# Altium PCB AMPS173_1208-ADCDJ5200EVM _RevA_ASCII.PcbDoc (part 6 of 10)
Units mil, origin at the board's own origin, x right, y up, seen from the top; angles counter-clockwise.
Board outline 10500 x 2750 mil, 14 copper layers (Top Copper, Layer 2 (GND1), Layer 3 (SIG1), Layer 4 (GND2, Layer 5 (PWR1), Layer 6 (GND3), Layer 7 (PWR/SIGNAL2), Layer 8 (PWR/SIGNAL3), Layer 9 (GND4), Layer 10 PWR2), Layer 11 (GND5), Layer 12 (SIG4), Layer 13 (GND6), Bottom Copper), stack 60.6 mil thick; 701 components, 826 nets, 3386 pads, 2128 vias.
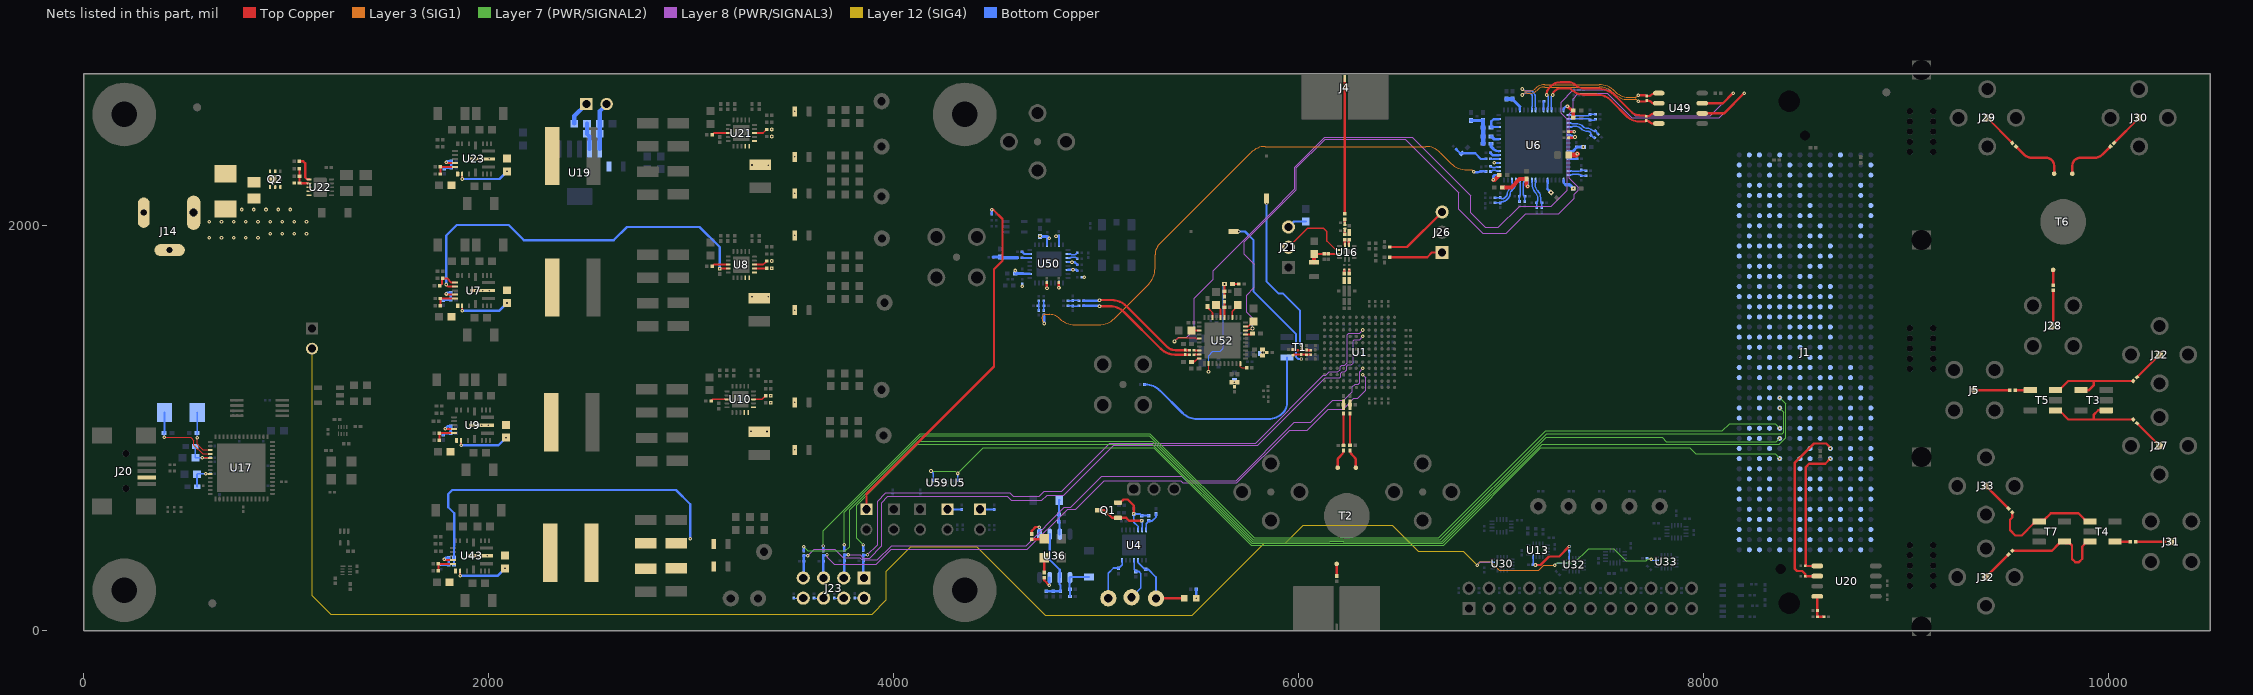
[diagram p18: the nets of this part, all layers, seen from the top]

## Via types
v1: diameter 18, hole 8, Top Copper to Bottom Copper, tented both sides, 1234 vias
v2: diameter 18, hole 8, Top Copper to Bottom Copper, tented top, 219 vias
v3: diameter 16, hole 8, Top Copper to Bottom Copper, tented both sides, 138 vias
v4: diameter 19.68, hole 7.87, Top Copper to Bottom Copper, 103 vias
v5: diameter 20, hole 10, Top Copper to Bottom Copper, tented top, 96 vias
v6: diameter 20, hole 10, Top Copper to Bottom Copper, tented both sides, 71 vias
v7: diameter 15.75/18/18/18/16/18/18/18/18/16/18/18/18/18 (per signal layer), hole 8, Top Copper to Bottom Copper, 50 vias
v8: diameter 20, hole 10, Top Copper to Bottom Copper, 40 vias
v9: diameter 15.75, hole 7.87, Top Copper to Bottom Copper, 28 vias
v10: diameter 21.81, hole 10, Top Copper to Bottom Copper, 26 vias
v11: diameter 15.75/16/16/16/16/16/16/16/16/16/16/16/16/18 (per signal layer), hole 8, Top Copper to Bottom Copper, 26 vias
v12: diameter 18, hole 8, Top Copper to Bottom Copper, tented bottom, 18 vias
v13: diameter 25.75, hole 15.75, Top Copper to Bottom Copper, 16 vias
v14: diameter 15.75/16/16/16/16/16/16/18/16/16/16/16/16/18 (per signal layer), hole 8, Top Copper to Bottom Copper, 15 vias
v15: diameter 30, hole 15, Top Copper to Bottom Copper, tented both sides, 12 vias
v16: diameter 15.75/16/16/16/18/16/16/16/16/16/16/16/16/18 (per signal layer), hole 8, Top Copper to Bottom Copper, 11 vias
v17: diameter 15.75/16/16/16/16/16/16/16/16/18/16/16/16/18 (per signal layer), hole 8, Top Copper to Bottom Copper, 7 vias
v18: diameter 15.75/16/16/16/16/16/16/18/16/18/16/16/16/18 (per signal layer), hole 8, Top Copper to Bottom Copper, 5 vias
v19: diameter 119.29, hole 77.95, Top Copper to Bottom Copper, 4 vias
v20: diameter 18, hole 8, Top Copper to Bottom Copper, 4 vias
v21: diameter 15.75/16/16/16/18/16/16/18/16/16/16/16/16/18 (per signal layer), hole 8, Top Copper to Bottom Copper, 2 vias
v22: diameter 15.75/16/16/16/16/16/18/16/16/16/16/16/16/18 (per signal layer), hole 8, Top Copper to Bottom Copper, 2 vias
v23: diameter 15.75/16/16/16/16/16/18/18/16/16/16/16/16/18 (per signal layer), hole 8, Top Copper to Bottom Copper, 1 vias

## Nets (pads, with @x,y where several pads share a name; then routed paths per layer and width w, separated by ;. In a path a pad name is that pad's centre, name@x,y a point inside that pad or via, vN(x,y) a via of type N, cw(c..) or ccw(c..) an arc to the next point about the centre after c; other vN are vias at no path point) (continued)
LMK_REF_P: C49.2 C507.1 R451.2 | length 2767
  Layer 3 (SIG1) w3.25: v1(4743.41,1517.62) 4740.27,1520.76 cw(c4760.17,1540.65) 4732.03,1540.65 4732.03,1547.03 cw(c4747,1547.03) 4747,1562 4769.46,1562 cw(c4769.46,1490.46) 4820.05,1541.05 ccw(c4893.18,1614.18) 4893.18,1510.75 5011.58,1510.75 ccw(c5011.58,1622) 5090.24,1543.33 5257.95,1711.05 ccw(c5179.99,1789.01) 5290.25,1789.01 5290.25,1857.26 cw(c5364.51,1857.26) 5312,1909.77 5763.94,2361.71 cw(c5834.65,2291) 5834.65,2391 6627.58,2391 cw(c6627.58,2291) 6698.29,2361.71 6751.67,2308.33 ccw(c6830.33,2387) 6830.33,2275.75 6853,2275.75 cw(c6853,2270.56) 6856.66,2274.24 v1(6864.58,2266.32)
  Bottom Copper w10.5: C507.1@4740,1558.98 cw(c4732.76,1551.73) 4743,1551.73 4743,1518.61 ccw(c4744.4,1518.61) v1(4743.41,1517.62) ; v1(6864.58,2266.32) ccw(c6868.97,2270.7) 6868.97,2264.5 6883.97,2264.5 ccw(c6883.97,2279.78) 6894.78,2268.98 R451.2@6900,2268.98 6911.69,2268.98 ccw(c6914.04,2271.33) 6914.04,2268 C49.2@6925,2268
LMX_CPOUT: C337.1 C338.1 R263.2 U52.12 | length 590.7
  Top Copper w6: U52.12@5554.13,1319.2 5554.21,1319.13 v1(5554.21,1278.79)
  Top Copper w10: R263.2@5633.21,1650.79 C338.1@5633.21,1676.79 v1(5633.21,1712.48) C337.1@5633.52,1712.79
  Bottom Copper w5: v1(5554.21,1278.79) 5554.21,1359.21 5575,1380 5612,1380 5626,1394 5626,1705.27 v1(5633.21,1712.48)
LMX_REF_N: C347.2 C506.1 R265.1 | length 615.5
  Top Copper w11.5: v1(5016,1603) 5066.58,1603 cw(c5066.58,1503) 5137.29,1573.71 5317.94,1393.06 ccw(c5388.65,1463.77) 5388.65,1363.77 R265.1@5439.21,1363.77 C347.2@5460.21,1363.79
  Bottom Copper w11.5: C506.1@4936.02,1605 5014,1605 v1(5016,1603)
LMX_REF_P: C346.2 C505.1 R265.2 | length 620.8
  Top Copper w11.5: v1(5016,1633) 5077.58,1633 cw(c5077.58,1533) 5148.29,1603.71 5348,1404 ccw(c5391.89,1447.89) 5391.89,1385.82 R265.2@5439.21,1385.82 C346.2@5460.21,1385.79
  Bottom Copper w11.5: C505.1@4936.02,1630 5013,1630 v1(5016,1633)
LMX_SYNC: U49.7 U52.5 | length 4574.9
  Top Copper w5: v1(5386.21,1428.79) 5404.21,1446.79 5489.21,1446.79 5492.78,1443.22 U52.5@5508.86,1443.22
  Top Copper w11.5: U49.7@7992.28,2605 8095,2605 v1(8145,2655)
  Layer 8 (PWR/SIGNAL3) w3.3: v1(5386.21,1428.79) 5406.41,1449 5447,1449 5485,1487 5485,1643 5577,1735 5577,1778.28 5921,2122.28 5921,2124.47 5980.35,2183.82 5980.35,2289.23 6129.12,2438 6560.54,2438 6849.85,2148.69 6849.85,2063.69 6921.54,1992 6985,1992 7090,2097 7246,2097 7325,2176 7325,2526 7295,2556 7295,2611 7356,2672 7533,2672 7662,2543 8033,2543 v1(8145,2655)
LMX_SYSREFREQ: U49.6 U52.28 | length 4460.5
  Top Copper w4: U52.28@5737.21,1482.59 5746,1482.59 5752.21,1488.79 5767.21,1488.79 v1(5771.21,1492.79)
  Top Copper w11.5: U49.6@7992.28,2555 8100,2555 v1(8200,2655)
  Layer 8 (PWR/SIGNAL3) w3.3: v1(5771.21,1492.79) 5771.21,1544.79 5742,1574 5742,1657 5781,1696 5781,1810 5731,1860 5731,1920.55 5988.65,2178.19 5988.65,2285.79 6130.85,2428 6525.54,2428 6790.85,2162.69 6790.85,2081 6907.85,1964 7024,1964 7120.16,2060.16 7283.16,2060.16 7359.45,2136.45 7359.45,2155.78 7379.35,2175.68 7379.35,2190 7335,2234.35 7335,2552.15 7355,2572.15 7355,2628 7381,2654 7524,2654 7645.5,2532.5 8077.5,2532.5 v1(8200,2655)
LMX_VTUNE: C336.1 R263.1 U52.35 | length 77.4
  Top Copper w8: U52.35@5632.87,1547.55 5632.87,1597.46 C336.1@5633.21,1597.79
  Top Copper w10: C336.1@5633.21,1597.79 R263.1@5633.21,1624.8
NCOA0_ADC: J23.1 R83.1 R84.2 U1.C7 | length 3269.9
  Layer 8 (PWR/SIGNAL3) w3.3: v3(3870,375) 3920,425 3920,640 3961,681 4573.01,681 4590,664 4719,664 4744,689 4829,689 5066.7,926.7 5786.7,926.7 6121,1261 6133,1261 6151.41,1279.41 6193.64,1279.41 6204.41,1290.19 6204.41,1303.41 6213,1312 6226.22,1312 6238.11,1323.88 6238.11,1461.11 6246.39,1469.39 6299.9,1469.39 v14(6315.75,1485.24)
  Bottom Copper w11.5: J23.1@3853,261 3850,264 R84.2@3850,345 3848.98,346.02 R83.1@3848.98,373.98 3868.98,373.98 v3(3870,375)
NCOA0_FMC: J1.H25 R83.2 | length 5579.3
  Layer 7 (PWR/SIGNAL2) w3.3: v3@3849.48,423.47 v3@3849.98,423.98
  Layer 7 (PWR/SIGNAL2) w4: v3(3848.98,423.98) 3817,455.95 3817,620.95 4118,921.95 5277.06,921.95 5767.84,431.18 6157.21,431.18 6158.17,432.14 6215.83,432.14 6216.79,431.18 6710.4,431.18 7201.18,921.95 8372,921.95 8404,953.95 8404,1121 v1(8375,1150)
  Bottom Copper w11.5: R83.2@3848.98,396.02 v3(3848.98,423.98)
NCOA1_ADC: J23.3 R87.1 R89.2 U1.D7 | length 3364.4
  Layer 8 (PWR/SIGNAL3) w3.3: v3(3775,375) 3834,375 3849.75,359.25 3880.26,359.25 3940,418.99 3940,632.99 3971.01,664 4561.01,664 4581,644 4731,644 4757,670 4840,670 5086.7,916.7 5796.7,916.7 6130.11,1250.11 6203.11,1250.11 6206.61,1253.61 6206.61,1272.02 6214,1279.41 6226.41,1279.41 6237,1290 6237,1307 6243,1313 6260,1313 6268,1321 6268,1431 6275,1438 6301.02,1438 v14@6316.76,1453.74
  Bottom Copper w11.5: J23.3@3753,261 3756.02,264.02 R89.2@3756.02,346.02 3755,347.05 R87.1@3755,375 v3(3775,375)
  other v14: 6315.75,1453.74
NCOA1_FMC: J1.H26 R87.2 | length 5546.8
  Layer 7 (PWR/SIGNAL2) w3.3: v3(3755,425) 3755,426.01 v3@3756.01,425
  Layer 7 (PWR/SIGNAL2) w4: v3@3755,426.01 3755,584.41 4133.54,962.95 5261.52,962.95 5775.29,449.18 6149.75,449.18 6150.72,450.14 6223.28,450.14 6224.25,449.18 6698.65,449.18 7223.43,973.95 8388,973.95 8395,980.95 8395,1080 v1(8375,1100)
  Bottom Copper w11.5: R87.2@3755,397.05 v3(3755,425)
NCOB0_ADC: J23.5 R91.1 R108.2 U1.K7 | length 3266.2
  Layer 8 (PWR/SIGNAL3) w3.3: v3@3671.01,375 3671.01,363 3705.5,328.5 3913.51,328.5 3987.01,402 4659.5,402 4858,600.5 4899.5,600.5 5040.25,741.25 5416.75,741.25 5427,731 5694.54,731 5954.23,990.69 6042.77,990.69 6146.48,1094.4 6219.07,1094.4 6272.22,1147.55 6291.94,1147.55 6331.4,1187 6331.4,1250.12 v14@6316.76,1264.76
  Bottom Copper w11.5: J23.5@3653,261 3652.4,261.6 R108.2@3652.4,343.19 3652.4,371.14 R91.1@3651.38,372.17 3667.17,372.17 v3(3670,375)
  other v14: 6315.75,1264.76
NCOB0_FMC: J1.H28 R91.2 | length 5480.1
  Layer 7 (PWR/SIGNAL2) w4: v3(3651.38,418.62) 3651.38,493.52 4129.81,971.95 5265.24,971.95 5779.02,458.18 6146.02,458.18 6146.99,459.14 6227.01,459.14 6227.98,458.18 6691.75,458.18 7220.73,987.16 8092.21,987.16 8128,1022.95 8352.05,1022.95 v1(8375,1000)
  Bottom Copper w11.5: v3@3650,420 v3(3651.38,418.62) R91.2@3651.38,394.21
NCOB1_ADC: J23.7 R109.1 R147.2 U1.J7 | length 3364
  Layer 8 (PWR/SIGNAL3) w3.3: v3@3576.01,370 3608.01,402 3709.01,402 3751.11,359.9 3833.1,359.9 3843.25,349.75 3918.76,349.75 3990.01,421 4653,421 4842,610 4874,610 5027.5,763.5 5422.5,763.5 5444,742 5690.16,742 5977.85,1029.69 6059.2,1029.69 6166.91,1137.4 6222.49,1137.4 6265,1179.91 6265,1204.65 6277.97,1217.62 6292.72,1217.62 6300.1,1225 6300.1,1279.6 v14@6316.76,1296.26
  Bottom Copper w11.5: J23.7@3553,261 3556.02,264.02 R147.2@3556.02,342.98 ; R147.2@3555,344 R109.1@3555,371.95 3573.05,371.95 v3(3575,370)
  other v14: 6315.75,1296.26
NCOB1_FMC: J1.H29 R109.2 | length 5619
  Layer 7 (PWR/SIGNAL2) w3.3: v3@3556.01,415 v3@3555.5,414.5 ; v3@3555.5,414.5 3555,413.99 v3(3555,415) v3@3555.5,414.5
  Layer 7 (PWR/SIGNAL2) w4: v3@3555.5,414.5 3576.05,393.95 3761,393.95 3782,414.95 3782,598.68 4119.27,935.95 5275.79,935.95 5771.56,440.18 6153.48,440.18 6154.44,441.14 6219.56,441.14 6220.52,440.18 6706.67,440.18 7221.45,954.95 7794,954.95 7814.95,934 8359,934 v1(8375,950)
  Bottom Copper w11.5: R109.2@3555,394 v3(3555,415)
NetC1_1: C1.1 U6.37 | length 42.3
  Bottom Copper w8: C1.1@6946.02,2330 6946.69,2329.33 6957.87,2329.33 6958.54,2330 6987.09,2330 U6.37@6987.09,2329.33
NetC1_2: C1.2 R30.2 R32.2 | length 165.7
  Bottom Copper w11.5: R32.2@6777.79,2377.2 6797.11,2357.89 R30.2@6804.7,2357.89 6804.93,2357.67 6871.33,2357.67 6899,2330 C1.2@6923.98,2330
NetC4_1: C4.1 R20.2 U4.7 | length 109.2
  Bottom Copper w9: U4.7@5246.31,498.28 5246.31,529.54 C4.1@5259.25,542.48 5276.75,542.48 5295,560.73 R20.2@5295,577.01
NetC4_2: C4.2 C5.2 Q1.2 R21.2 U4.5 | length 303.2
  Top Copper w11.5: Q1.2@5107.24,632.4 5118.4,632.4 5134,648 5155,648 5185,618 v1(5185,577.01)
  Bottom Copper w9: U4.5@5206.94,498.28 5206.94,515 5185,536.94 v1(5185,577.01) 5215.71,577.01 C5.2@5224.25,568.46 C4.2@5259.25,568.46
NetC5_1: C5.1 Q1.1 Q1.3 U4.6 | length 278.4
  Top Copper w11.5: Q1.3@5012.76,595 5040,595 5077.4,557.6 Q1.1@5107.24,557.6 5147.4,557.6 5162.52,542.48 v1(5224.25,542.48)
  Bottom Copper w9: v1(5224.25,542.48) 5226.62,540.11 U4.6@5226.62,498.28
NetC6_1: C6.1 U6.38 | length 45.6
  Bottom Copper w11.5: C6.1@6946.02,2360 6957.01,2349.02 U6.38@6987.09,2349.02
NetC7_1: C7.1 C228.1 FB3.1 FB5.1 FB6.1 FB7.1 R135.2 U21.1 U21.19 U21.20
  other v1: 3510.57,1953.02 3510.57,2160.02 3379.15,2299.13 3300,2300 3510.57,2340.02 3397.99,2440.75 3397.99,2475.75 3510.57,2565.02
NetC45_1: C45.1 C73.2 R1.2 R171.1 R172.2 | length 88.1
  Top Copper w11.5: C45.1@5972.02,1359.98 cw(c5981.62,1350.38) 5981.62,1363.95 R172.2@6013,1363.95 R171.1@6059,1364 R171.1@6059,1364
NetC46_1: C46.1 C98.2 R2.2 R172.1 R174.1 | length 87.8
  Top Copper w12: C46.1@5972.02,1389 ccw(c5979.27,1396.24) 5979.27,1386 C98.2@6013,1386 R174.1@6059,1386
NetC47_1: C47.1 C48.1 L3.2 U6.10 U6.33 U6.36 | length 188.3
  Top Copper w20: v1(6960.46,2226.81) 6967.13,2226.81 C47.1@6990.31,2250
  Bottom Copper w10: v1(6966,2312) ccw(c6970.24,2316.24) 6970.24,2310.24 U6.36@6987.09,2310.24
  Bottom Copper w11.5: 6960.46,2245.46 6965.59,2250.59 U6.33@6987.09,2250.59 ; U6.10@7333.54,2368.7 7353.7,2368.7
  Bottom Copper w15: v1(6960.46,2226.81) 6960.46,2245.46 ; 7353.7,2368.7 7373.98,2388.98 v1(7405,2388.98)
NetC49_1: C49.1 U6.34 | length 42.3
  Bottom Copper w7: C49.1@6947.05,2268 cw(c6960.84,2254.2) 6960.84,2273.71 6968.93,2273.71 cw(c6968.93,2264.01) 6975.8,2270.87 U6.34@6987.09,2270.87
NetC50_1: C50.1 U6.35 | length 42.2
  Bottom Copper w7: C50.1@6947.05,2293 ccw(c6959.81,2305.76) 6959.81,2287.71 6968.93,2287.71 ccw(c6968.93,2297.42) 6975.8,2290.56 U6.35@6987.09,2290.56
NetC53_2: C53.2 L4.2 U6.17 | length 72
  Top Copper w11.5: v1(7355,2185.32) C53.2@7355.31,2185
  Bottom Copper w11.5: U6.17@7307.95,2225 7307.95,2212.05 7317.5,2202.5
  Bottom Copper w15: 7317.5,2202.5 7337.81,2202.5 v1(7355,2185.32) L4.2@7355.31,2185
NetC54_2: C54.2 L5.2 U6.21 | length 68.9
  Bottom Copper w11.5: 7228.15,2209.7 7229.21,2210.76 U6.21@7229.21,2225 ; v1(7245.77,2164.23) C54.2@7246.08,2163.92
  Bottom Copper w12: 7228.15,2181.85 7228.15,2209.7
  Bottom Copper w15: 7228.15,2181.85 v1(7245.77,2164.23)
NetC55_2: C55.2 L7.2 U6.26 | length 204.7
  Top Copper w20: L7.2@7004.69,2190 7050,2190 7090.31,2230.31 C55.2@7125,2230.31 7125,2200 v1(7130,2195)
  Bottom Copper w11.5: v1(7130,2195) 7130.79,2195.79 U6.26@7130.79,2225
NetC56_2: C56.2 L11.2 U6.53 | length 98.9
  Bottom Copper w11.5: U6.53@7091.42,2571.46 7091.42,2588.9
  Bottom Copper w15: L11.2@7055,2625.31 7091.42,2588.9
  Bottom Copper w20: C56.2@7025,2625.31 L11.2@7055,2625.31
NetC57_2: C57.2 L12.2 U6.64 | length 101
  Top Copper w15.5: v1(7326.65,2590.63) 7347.28,2570 L12.2@7355.31,2570 C57.2@7355.31,2535
  Bottom Copper w10: U6.64@7307.95,2571.46 7307.95,2572.25 cw(c7325.75,2572.25) v1@7325.75,2590.05
NetC58_1: C58.1 C59.1 L6.2 L8.1 L9.1 L10.1 | length 176.6
  Bottom Copper w11.5: L6.2@6850,2520.31 L6.2@6851.34,2518.98 ; C58.1@6908.66,2518.98 C58.1@6910,2520.32 ; L10.1@6910,2485.31 L10.1@6910.31,2485
  Bottom Copper w15: L6.2@6851.34,2518.98 C59.1@6880,2518.98 C58.1@6908.66,2518.98
  Bottom Copper w20: L10.1@6910,2485.31 C58.1@6910,2520.32
  Bottom Copper w22: L8.1@6910.31,2405 L10.1@6910.31,2485
NetC64_1: C64.1 U6.11 | length 88.4
  Top Copper w25: C64.1@7332.56,2350 7370,2350 v1(7375,2355)
  Bottom Copper w11.5: U6.11@7333.54,2349.02 7369.02,2349.02 v1(7375,2355)
NetC65_1: C65.1 U6.12 | length 40.7
  Bottom Copper w11.5: U6.12@7333.54,2329.33 7373.31,2329.33 C65.1@7373.98,2330
NetC67_1: C67.1 U43.2 | length 260.7
  Top Copper w9.8: v1(1858.9,271.1) U43.2@1858.9,295.2
  Bottom Copper w11.5: v1(1858.9,271.1) 2042.6,271.1 v1(2080,308.5)
NetC67_2: C67.2 L27.1 U43.9
  other v9: 1926.61,370 1959.29,370 1991.97,370
NetC73_1: C73.1 J11.1 | length 785.5
  Bottom Copper w10: v3(5703.35,1971.69) 5734.26,1971.69 5776,1929.95 5776,1676.25 5986,1466.25 5986,1352.95 5997.05,1341.91 v3(6013,1341.91)
NetC74_1: C74.1 C90.1 R22.1 | length 158
  Top Copper w11.5: C74.1@6221,915.02 R22.1@6221,1073.01
NetC75_1: C75.1 T2.1 | length 60
  Top Copper w11.5: C75.1@6187,270.04 T2.1@6187,330.04
NetC83_1: C83.1 C84.2 L14.2 U17.9 | length 149.5
  Top Copper w6: v1(602.47,774.97) U17.9@624.82,774.97
  Bottom Copper w8: C83.1@560,772.5 562.47,774.97 v1(602.47,774.97) C84.2@624.93,774.97
  Bottom Copper w10: L14.2@559.62,711.5 560,711.87 C83.1@560,772.5
NetC85_1: C85.1 C86.2 L15.2 U17.5 | length 171.7
  Top Copper w8: v1(584.71,853.71) U17.5@624.82,853.71
  Bottom Copper w8: C85.1@550.5,853.5 C85.1@550.71,853.71 ; L15.2@551.12,910.5 551.12,854.13 C85.1@550.71,853.71 ; C86.2@624.98,853.5 584.93,853.5 v1(584.71,853.71) C85.1@550.71,853.71
NetC87_1: C87.1 U17.3 Y1.1 | length 235.1
  Top Copper w5: v1(560,953) 560,921 587.92,893.08 U17.3@624.82,893.08
  Bottom Copper w5: C87.1@559.68,977 560,976.68 v1(560,953)
  Bottom Copper w8: Y1.1@558.98,1076.98 Y1.1@560,1078 560,977.32 C87.1@559.68,977
NetC88_1: C88.1 U17.4 Y1.2 | length 400.1
  Top Copper w5: v1(397,955) 528,955 544,939 544,917 587.6,873.4 U17.4@624.82,873.4
  Bottom Copper w5: C88.1@396.32,976 397,975.32 v1(397,955)
  Bottom Copper w8: C88.1@396.32,976 398.58,978.27 Y1.2@398.58,1078 Y1.2@397.61,1077.02
NetC90_2: C90.2 T2.3 | length 95
  Top Copper w11.5: T2.3@6192,805.04 6192,841.51 cw(c6212.49,841.51) 6198,856 6213.19,871.19 ccw(c6194.35,890.04) C90.2@6221,890.04
NetC91_1: C91.1 C93.1 R23.1 | length 157
  Top Copper w11.5: C91.1@6253,916.02 R23.1@6253,1073.01
NetC91_2: C91.2 T2.2 | length 95
  Top Copper w11.5: C91.2@6253,890.04 ccw(c6279.65,890.04) 6260.81,871.19 6276,856 cw(c6261.51,841.51) 6282,841.51 T2.2@6282,805.04
NetC92_1: C92.1 R215.2 R217.2 U20.8 | length 133.2
  Top Copper w11.5: U20.8@8560.31,170 8561.02,169.29 C92.1@8561.02,100 R217.2@8561.02,70 R215.2@8593.98,70
NetC94_1: C94.1 C95.1 C97.1 FB1.2 U16.9 | length 165.8
  Top Copper w10: C97.1@6076,1860.49 6076.51,1861 C94.1@6126,1861 C95.1@6146,1861 6146.75,1860.25 U16.9@6200.66,1860.25
  Top Copper w20: FB1.2@6076,1819.87 C97.1@6076,1860.49
NetC98_1: C98.1 J9.1 | length 785.5
  Bottom Copper w10: v3(5841.12,2109.45) 5841.12,1723.84 5899,1665.95 5921,1665.95 6005,1581.95 6005,1416.05 v3(6013,1408.05)
NetC99_1: C99.1 R181.1
NetC99_2: C99.2 R180.2 | length 18
  Top Copper w11.5: C99.2@6248.92,1763.99 R180.2@6248.92,1782.01
NetC101_1: C101.1 C102.1 C103.1 C104.1 C117.1 FB2.1 FB8.1 L27.2 R229.2 | length 1764.9
  Bottom Copper w11.5: C117.1@1827.99,325 R229.2@1827.99,360 1827.99,417.99 1829.25,419.25 1829.25,580.75 1800,610 1800,675 1820,695 2925,695 2995,625 v1(2995,455)
NetC105_1: C105.1 R186.1
NetC105_2: C105.2 R185.2 | length 18
  Top Copper w11.5: C105.2@6224.92,1763.99 R185.2@6224.92,1782.01
NetC106_2: C106.2 L13.1 R6.2 | length 16.9
  Top Copper w11.5: C106.2@6227.23,2015.72 R6.2@6227.23,2032.62
NetC107_1: C107.1 U16.6 | length 22.8
  Top Copper w11.5: U16.6@6227.23,1906.51 C107.1@6227.23,1929.35
NetC107_2: C107.2 C118.2 L13.2 | length 17
  Top Copper w11.5: C107.2@6227.23,1957.49 C118.2@6227.23,1974.49
NetC108_1: C108.1 U16.5 | length 28.9
  Top Copper w10: C108.1@6246.92,1929.35 C108.1@6249.08,1931.51 ; C108.1@6246.92,1931.51 C108.1@6249.08,1929.35
  Top Copper w11.5: U16.5@6246.92,1906.51 C108.1@6246.92,1929.35
NetC108_2: C108.2 R193.2 | length 16.5
  Top Copper w10: R193.2@6246.84,1973.94 6246.84,1957.57 C108.2@6246.92,1957.49
NetC115_2: C115.2 R228.1 U43.22 | length 107.5
  Top Copper w9.8: C115.2@1750.98,295.75 R228.1@1750.98,330.75 1751.1,330.63 U43.22@1823.46,330.63
NetC116_2: C116.2 U43.1
NetC117_2: C117.2 R229.1 R232.2 U43.21 | length 149.3
  Top Copper w9.8: v1(1780,353.37) 1776.74,353.37 1779.8,350.31 U43.21@1823.46,350.31
  Bottom Copper w11.5: R232.2@1765,327.99 1767.99,325 C117.2@1802.01,325 R229.1@1802.01,360 1786.63,360 v1(1780,353.37)
NetC119_1: C119.1 T5.6 | length 75
  Top Copper w11.5: C119.1@9537.5,1188.48 T5.6@9612.5,1188.48
NetC119_2: C119.2 J5.1 | length 175
  Top Copper w11.5: J5.1@9336.52,1188.48 C119.2@9511.52,1188.48
NetC120_1: C120.1 J22.1 | length 157.9
  Top Copper w11.5: C120.1@10139.25,1251.86 J22.1@10250.87,1363.48
NetC120_2: C120.2 T3.6 T5.1 | length 496.8
  Top Copper w11.5: T5.1@9737.5,1188.48 9755,1188.48 9800,1233.48 9939.52,1233.48 10116.2,1233.48 10116.76,1232.93 10120.32,1232.93 C120.2@10120.87,1233.48 ; T3.6@9862.5,1188.48 9902.48,1188.48 9925,1211 9925,1233.48
NetC121_1: C121.1 J27.1 | length 157.9
  Top Copper w11.5: C121.1@10139.25,1025.11 J27.1@10250.87,913.48
NetC121_2: C121.2 T3.3 T5.3 | length 496.8
  Top Copper w11.5: T5.3@9737.5,1088.48 9755,1088.48 9800,1043.48 9925,1043.48 ; T3.3@9987.5,1088.48 9947.52,1088.48 9925,1065.97 9925,1043.48 ; C121.2@10120.87,1043.48 10120.32,1044.04 10116.76,1044.04 10116.2,1043.48 9925,1043.48
NetC122_1: C122.1 T6.1 | length 75
  Top Copper w11.5: C122.1@9725,1706.98 T6.1@9725,1781.98
NetC122_2: C122.2 J28.1 | length 175
  Top Copper w11.5: J28.1@9725,1506 C122.2@9725,1681
NetC123_1: C123.1 T6.3 | length 270.6
  Top Copper w11.5: C123.1@9542.12,2390.85 9581.4,2351.56 ccw(c9619,2389.19) 9619,2336 9690.98,2336 cw(c9690.98,2296.98) 9730,2296.98 T6.3@9730,2256.98
NetC123_2: C123.2 J29.1 | length 175
  Top Copper w11.5: J29.1@9400,2532.97 C123.2@9523.74,2409.22
NetC127_1: C127.1 T6.2 | length 270.6
  Top Copper w11.5: T6.2@9820,2256.98 9820,2296.98 cw(c9859.02,2296.98) 9859.02,2336 9931,2336 ccw(c9931,2389.19) 9968.6,2351.56 C127.1@10007.88,2390.85
NetC127_2: C127.2 J30.1 | length 175
  Top Copper w11.5: C127.2@10026.26,2409.22 J30.1@10150,2532.97
NetC129_1: C129.1 U7.2 | length 260.7
  Top Copper w9.8: v1(1868.9,1581.1) U7.2@1868.9,1605.2
  Bottom Copper w11.5: v1(1868.9,1581.1) 2052.6,1581.1 v1(2090,1618.5)
NetC129_2: C129.2 L1.1 U7.9
  other v9: 1936.61,1680 1969.29,1680 2001.97,1680
NetC136_2: C136.2 R93.1 U7.22 | length 107.5
  Top Copper w9.8: C136.2@1760.98,1605.75 R93.1@1760.98,1640.75 1761.1,1640.63 U7.22@1833.46,1640.63
NetC137_2: C137.2 U7.1
NetC138_1: C138.1 T4.6 | length 75
  Top Copper w11.5: T4.6@10031.5,440 C138.1@10106.5,440
NetC138_2: C138.2 J31.1 | length 175
  Top Copper w11.5: C138.2@10132.48,440 J31.1@10307.48,440
NetC143_2: C143.2 R96.1 R97.2 U7.21 | length 152.5
  Top Copper w9.8: v1(1790,1663.37) 1786.74,1663.37 1789.8,1660.32 U7.21@1833.46,1660.31
  Bottom Copper w11.5: R97.2@1775,1632.99 1777.01,1635 C143.2@1812.01,1635 R96.1@1812.01,1670 1796.63,1670 v1(1790,1663.37) v1@1790,1667
NetC144_1: C144.1 U8.13 | length 82.4
  Top Copper w9: C144.1@3102.99,1800 3110.99,1808 U8.13@3182.04,1808
NetC148_1: C148.1 J32.1 | length 157.9
  Top Copper w11.5: J32.1@9393.13,265 C148.1@9504.75,376.63
NetC148_2: C148.2 T4.1 T7.6 | length 562.2
  Top Copper w11.5: C148.2@9523.13,395 9523.68,395.56 9719.56,395.56 9754.75,430.75 9764,440 T7.6@9781.5,440 9790.75,430.75 9808.25,430.75 9818,421 9818,355 9834,339 9852.6,339 9869,355.4 9869,415.99 9879.75,426.74 9879.75,430.75 9889,440 T4.1@9906.5,440
NetC149_1: C149.1 J33.1 | length 157.9
  Top Copper w11.5: J33.1@9393.13,715 C149.1@9504.75,603.37
NetC149_2: C149.2 T4.3 T7.3 | length 560.9
  Top Copper w11.5: C149.2@9523.13,585 9523.68,584.44 9523.68,580.88 9523.13,580.33 9523.13,559.31 9511.95,548.14 9511.95,497.08 9538.26,470.78 9569.78,470.78 9629.75,530.75 9639,540 T7.3@9656.5,540 9665.75,549.25 9683.25,549.25 9714,580 9850,580 9879.75,550.25 9879.75,549.25 9889,540 T4.3@9906.5,540
NetC164_1: C164.1 C244.1 FB9.1 R98.2 U8.1 U8.19 U8.20
  other v1: 3510.57,1583.02 3379.15,1649.13 3300,1650 3397.99,1790.75 3397.99,1825.75
NetC164_2: C164.2 U8.3 | length 67.4
  Top Copper w9: U8.3@3311.96,1808 3354.26,1808 C164.2@3372.01,1825.75
NetC165_1: C165.1 U9.2 | length 260.7
  Top Copper w9.8: v1(1863.9,916.1) U9.2@1863.9,940.2
  Bottom Copper w11.5: v1(1863.9,916.1) 2047.6,916.1 v1(2085,953.5)
NetC165_2: C165.2 L2.1 U9.9
  other v9: 1931.61,1015 1964.29,1015 1996.97,1015
NetC192_2: C192.2 R114.1 U9.22 | length 107.5
  Top Copper w9.8: C192.2@1755.98,940.75 R114.1@1755.98,975.75 1756.1,975.63 U9.22@1828.46,975.63
NetC193_2: C193.2 U9.1
NetC194_2: C194.2 R115.1 R121.2 U9.21 | length 158
  Top Copper w9.8: v1(1785,998.37) 1781.74,998.37 1784.8,995.31 U9.21@1828.46,995.31
  Bottom Copper w11.5: R121.2@1775,967.99 1782.01,975 R115.1@1812.01,975 C194.2@1812.01,1010 1796.63,1010 v1(1785,998.37)
NetC199_1: C199.1 U10.13 | length 82.4
  Top Copper w9: C199.1@3097.99,1135 3105.99,1143 U10.13@3177.04,1143
NetC200_1: C200.1 C245.1 FB10.1 FB11.1 R118.2 U10.1 U10.19 U10.20
  other v1: 3510.57,893.02 3374.15,984.13 3295,985 3392.99,1125.75 3510.57,1128.02 3392.99,1160.75
NetC200_2: C200.2 U10.3 | length 67.4
  Top Copper w9: U10.3@3306.96,1143 3349.26,1143 C200.2@3367.01,1160.75
NetC208_1: C208.1 U23.2 | length 260.7
  Top Copper w9.8: v1(1868.9,2231.1) U23.2@1868.9,2255.2
  Bottom Copper w11.5: v1(1868.9,2231.1) 2052.6,2231.1 v1(2090,2268.5)
NetC208_2: C208.2 L17.1 U23.9
  other v9: 1936.61,2330 1969.29,2330 2001.97,2330
NetC220_2: C220.2 R131.1 U23.22 | length 107.5
  Top Copper w9.8: C220.2@1760.98,2255.75 R131.1@1760.98,2290.75 1761.1,2290.63 U23.22@1833.46,2290.63
NetC221_2: C221.2 U23.1
NetC222_2: C222.2 R133.1 R138.2 U23.21 | length 147.9
  Top Copper w9.8: v1(1790,2313.37) 1786.74,2313.37 1789.8,2310.31 U23.21@1833.46,2310.31
  Bottom Copper w11.5: R138.2@1780,2282.99 1782.01,2285 C222.2@1814.02,2285 R133.1@1814.02,2320 1796.63,2320 v1(1790,2313.37)
NetC227_1: C227.1 U21.13 | length 82.4
  Top Copper w9: C227.1@3102.99,2450 3110.99,2458 U21.13@3182.04,2458
NetC228_2: C228.2 U21.3 | length 67.4
  Top Copper w9: U21.3@3311.96,2458 3354.26,2458 C228.2@3372.01,2475.75
NetC235_1: C235.1 D7.2 J14.1 Q2.3 R144.2 U22.3 U22.4 U22.5
  other v1: 620,1940 680,1940 740,1940 800,1940 860,1940 920,1960 980,1960 1040,1960 1100,1960 620,2020 680,2020 740,2020 800,2020 860,2020 920,2020 980,2020 1040,2020 1100,2020 780,2080 840,2080 900,2080 960,2080 1020,2080
NetC235_2: C235.2 D7.1 J14.2 Q2.1 Q2.2 Q2.5 Q2.6 Q2.8
NetC241_1: C241.1 R144.1 R146.1 U22.2 | length 116.2
  Top Copper w11.5: C241.1@1064.61,2281 1065,2280.61 R146.1@1065,2245 ; R144.1@1065.05,2211 R146.1@1065.05,2244.95 ; R144.1@1066.37,2209.69 U22.2@1112.44,2209.69
NetC242_1: C242.1 U22.1 | length 126
  Top Copper w11.5: C242.1@1064.61,2319 1083,2319 1094,2308 1094,2238 1102.63,2229.37 U22.1@1112.44,2229.37
NetC285_1: C285.1 T1.3 | length 1032.1
  Bottom Copper w10: C285.1@5239,1216 5243.58,1216 cw(c5243.58,1116) 5314.29,1186.71 5425.71,1075.29 ccw(c5496.42,1146) 5496.42,1046 5850.58,1046 ccw(c5850.58,1146) 5921.29,1075.29 ccw(c5871.76,1124.81) 5941.8,1124.81 T1.3@5941.8,1350
NetC287_2: C287.2 D5.1 R176.2 U36.5 | length 189
  Bottom Copper w11.5: U36.5@4867.99,262.28 4867.99,206.26 R176.2@4870,204.25 C287.2@4870,169.25 ; U36.5@4870,262.72 4872.81,265.53 D5.1@4964,265.53
NetC288_2: C288.2 R177.1 R216.2 U36.2 U36.6 | length 374.1
  Bottom Copper w11.5: R177.1@4752.99,195.55 C288.2@4787.99,195.55 R216.2@4822.99,195.55 4822.99,225 4817.99,230 U36.6@4817.99,262.28 ; U36.2@4770,477.28 4770,351 4820,301 U36.6@4820,262.72
NetC310_1: C310.1 C311.1 C312.1 C313.1 C314.1 L31.1 U50.2 U50.5 U50.20 U50.23 U50.30 | length 288.8
  Top Copper w11.5: C310.1@4755,1718.98 4755,1694.97 ccw(c4759.97,1694.97) v1(4756.46,1691.46) ; C311.1@4815,1718.98 4815,1694.49 v1(4815.51,1694.49)
  Bottom Copper w11.5: v1(4722.09,1947.4) L31.1@4723.43,1946.06 ; v1(4756.46,1691.46) U50.5@4756.46,1717.09 ; U50.20@4756.46,1906.06 C313.1@4756.46,1939 ; C313.1@4757.09,1946.06 4760.94,1946.06 v1(4768,1939) ; v1(4800.98,1949.02) 4802,1948 4802.98,1948.98 C314.1@4815,1948.98 4815.51,1948.46 U50.23@4815.51,1906.06 ; v1(4815.51,1694.49) U50.2@4815.51,1717.09 ; U50.30@4860.79,1782.05 v1(4885,1782.05) 4901.1,1782.05 C312.1@4906.06,1777.09
  Bottom Copper w15: L31.1@4723.43,1946.06 C313.1@4757.09,1946.06
NetC317_1: C317.1 C318.1 L32.2 R239.2 R241.2 U50.10 U50.28 | length 138
  Bottom Copper w11.5: v1(4600,1778.78) 4599.69,1778.46 L32.2@4599.69,1765 ccw(c4602.16,1767.47) L32.2@4602.16,1763.98 ; C318.1@4635,1763.98 ccw(c4638.9,1767.87) 4638.9,1762.36 U50.10@4671.81,1762.36 ; U50.28@4860.79,1821.42 4891.73,1821.42 C317.1@4906.06,1807.09
  Bottom Copper w15: L32.2@4602.16,1763.98 C318.1@4635,1763.98
  other v1: 4635,1701.38 4940.71,1745.28 4880,1820
NetC319_1: C319.1 U50.14 | length 39.1
  Bottom Copper w11.5: C319.1@4633.11,1842.09 4634.09,1841.1 U50.14@4671.81,1841.1
NetC319_2: C319.2 R245.2 R248.2 | length 121.5
  Bottom Copper w11.5: R248.2@4524.69,1845 R248.2@4525,1845.31 R248.2@4528.23,1842.09
  Bottom Copper w15.5: R245.2@4491.02,1845 R248.2@4524.69,1845 ; R248.2@4528.23,1842.09 C319.2@4611.06,1842.09
NetC320_1: C320.1 U50.15 | length 43.4
  Bottom Copper w11.5: C320.1@4633.11,1872.09 4644.41,1860.79 U50.15@4671.81,1860.79
NetC321_1: C321.1 U50.27 | length 48.4
  Bottom Copper w7: U50.27@4860.79,1841.1 4872.08,1841.1 cw(c4878.94,1834.24) 4878.94,1843.95 4894.45,1843.95 cw(c4894.45,1832.48) 4902.56,1840.59 C321.1@4906.06,1837.09
NetC322_1: C322.1 U50.26 | length 49.5
  Bottom Copper w7: U50.26@4860.79,1860.79 4872.08,1860.79 ccw(c4878.94,1867.65) 4878.94,1857.95 4894,1857.95 ccw(c4894,1865) 4898.98,1860 C322.1@4906.06,1867.09
NetC324_1: C324.1 L33.1 R252.2 R253.2
  other v3: 5820.91,1374.19
NetC333_1: C333.1 L35.1 R258.2 R259.2
  other v1: 5682.21,1226.79
NetC337_2: C337.2 R264.2 | length 31.3
  Top Copper w11.5: C337.2@5672.89,1712.79 R264.2@5704.21,1712.79
NetC339_2: C339.2 U52.10 | length 41.5
  Top Copper w8: C339.2@5474.45,1327.79 5484.21,1327.79 5501.21,1344.79 U52.10@5508.86,1344.79
NetC340_2: C340.2 U52.36 | length 71.4
  Top Copper w8: C340.2@5591.21,1609.79 5613.19,1587.81 U52.36@5613.19,1547.55
NetC341_2: C341.2 U52.38 | length 64
  Top Copper w8: C341.2@5550.21,1601.79 5550.21,1594.79 5573.82,1571.18 U52.38@5573.82,1547.55
NetC342_2: C342.2 U52.29 | length 49.6
  Top Copper w8: U52.29@5737.21,1502.28 5750.69,1502.28 C342.2@5776.21,1527.79
NetC343_2: C343.2 U52.3 | length 38.7
  Top Copper w8: C343.2@5470.21,1482.79 5508.65,1482.79 U52.3@5508.86,1482.59
NetC344_2: C344.2 U52.27 | length 35.9
  Top Copper w8: U52.27@5737.21,1462.91 5767.63,1462.91 C344.2@5771.52,1466.79
NetC345_2: C345.2 U52.33 | length 73
  Top Copper w8: U52.33@5672.24,1547.55 5672.24,1577.83 5698.21,1603.79 C345.2@5698.21,1609.79
NetC346_1: C346.1 U52.8 | length 27.3
  Top Copper w8: C346.1@5482.25,1385.79 5483.88,1384.16 U52.8@5508.86,1384.16
NetC347_1: C347.1 U52.9 | length 26.9
  Top Copper w8: C347.1@5482.25,1363.79 5482.94,1364.48 U52.9@5508.86,1364.48
NetC405_2: C405.2 D4.1 R164.2 U36.3 | length 170
  Bottom Copper w11.5: D4.1@4817.46,644.57 4815.47,642.58 C405.2@4815.47,574.57 4815,574.09 R164.2@4815,538.82 4817.99,535.83 U36.3@4817.99,476.85
NetC505_2: C505.2 R240.2 R244.2 | length 54.8
  Bottom Copper w7: R240.2@4860,1630 4880.41,1630 ccw(c4880.41,1635.04) R244.2@4883.98,1631.48 4910.41,1631.48 cw(c4910.41,1626.44) C505.2@4913.98,1630
NetC506_2: C506.2 R242.2 R243.2 | length 54.8
  Bottom Copper w7: R242.2@4860,1605 4880.41,1605 cw(c4880.41,1599.96) R243.2@4883.98,1603.52 4910.41,1603.52 ccw(c4910.41,1608.56) C506.2@4913.98,1605
NetC507_2: C507.2 R246.2 R250.2 | length 49
  Bottom Copper w7: C507.2@4740,1581.02 R246.2@4740,1630
NetC508_2: C508.2 R247.2 R249.2 | length 50.3
  Bottom Copper w7: C508.2@4715,1581.02 4715,1599.99 ccw(c4706.46,1599.99) R249.2@4712.5,1606.02 ccw(c4706.46,1612.06) 4715,1612.06 R247.2@4715,1630
NetD1_1: D1.1 R29.2 | length 44.9
  Bottom Copper w11.5: R29.2@5492.99,205 5492.99,161.26 v1(5493.78,160.47)
NetD1_2: D1.2 R26.1 TP4.1 U4.10 | length 375.6
  Top Copper w11.5: TP4.1@5295,160 5295.47,160.47 D1.2@5434.72,160.47
  Bottom Copper w9: U4.10@5206.94,348.67 5206.94,335 5238.94,302.99 R26.1@5245,302.99 5257.01,302.99 5295,265 TP4.1@5295,160
NetD2_1: D2.1 R67.2 | length 62.9
  Top Copper w11.5: R67.2@4682,452.01 4740.67,452.01 D2.1@4743.66,455
NetD3_1: D3.1 R68.2 | length 71.8
  Top Copper w11.5: R68.2@4742.99,287.56 D3.1@4742.99,359.33
NetFB4_1: FB4.1 R5.2 R198.2 U19.4 | length 116.7
  Bottom Copper w20: R198.2@2485.01,2454 R5.2@2485.01,2504 ; R198.2@2494.69,2444.31 2498,2441.01 U19.4@2498,2379
NetJ1_A22: J1.A22
NetJ1_A23: J1.A23
NetJ1_A26: J1.A26
NetJ1_A27: J1.A27
NetJ1_A30: J1.A30
NetJ1_A31: J1.A31
NetJ1_A34: J1.A34
NetJ1_A35: J1.A35
NetJ1_A38: J1.A38
NetJ1_A39: J1.A39
NetJ1_B1: J1.B1
NetJ1_B24: J1.B24
NetJ1_B25: J1.B25
NetJ1_B28: J1.B28
NetJ1_B29: J1.B29
NetJ1_B32: J1.B32
NetJ1_B33: J1.B33
NetJ1_B36: J1.B36
NetJ1_B37: J1.B37
NetJ1_B40: J1.B40
NetJ1_C2: J1.C2
NetJ1_C3: J1.C3
NetJ1_C10: J1.C10
NetJ1_C11: J1.C11
NetJ1_C14: J1.C14
NetJ1_C15: J1.C15
NetJ1_C16: J1.C16
NetJ1_C18: J1.C18
NetJ1_C19: J1.C19
NetJ1_C22: J1.C22
NetJ1_C23: J1.C23
NetJ1_C30: J1.C30 R807.2 U20.6 | length 883.8
  Top Copper w11.5: U20.6@8560.31,270 R807.2@8501.02,270 8501.02,280 8486.02,295 8460,295 8450,305 8450,830.9 8544.1,925 8605,925 8625,905 v2(8625,900)
NetJ1_C31: J1.C31 R808.2 U20.5 | length 687.5
  Top Copper w11.5: U20.5@8560.31,320 R808.2@8501.02,320 8504.25,323.23 8504.25,808.59 8520,824.34 8520,825 8600,825 v2(8625,850)
NetJ1_C35: J1.C35
NetJ1_C37: J1.C37
NetJ1_C39: J1.C39
NetJ1_D8: J1.D8
NetJ1_D9: J1.D9
NetJ1_D11: J1.D11
NetJ1_D12: J1.D12
NetJ1_D14: J1.D14
NetJ1_D15: J1.D15
NetJ1_D16: J1.D16
NetJ1_D17: J1.D17
NetJ1_D18: J1.D18
NetJ1_D20: J1.D20
NetJ1_D21: J1.D21
NetJ1_D23: J1.D23
NetJ1_D24: J1.D24
NetJ1_D29: J1.D29
NetJ1_D33: J1.D33
NetJ1_D34: J1.D34
NetJ1_D36: J1.D36
NetJ1_D38: J1.D38
NetJ1_D40: J1.D40
NetJ1_E2: J1.E2
NetJ1_E3: J1.E3
NetJ1_E6: J1.E6
NetJ1_E7: J1.E7
NetJ1_E9: J1.E9
NetJ1_E10: J1.E10
NetJ1_E12: J1.E12
NetJ1_E13: J1.E13
NetJ1_E15: J1.E15
NetJ1_E16: J1.E16
NetJ1_E17: J1.E17
NetJ1_E18: J1.E18
NetJ1_E19: J1.E19
NetJ1_E21: J1.E21
NetJ1_E22: J1.E22
NetJ1_E24: J1.E24
NetJ1_E25: J1.E25
NetJ1_E27: J1.E27
NetJ1_E28: J1.E28
NetJ1_E30: J1.E30
NetJ1_E31: J1.E31
NetJ1_E33: J1.E33
NetJ1_E34: J1.E34
NetJ1_E36: J1.E36
NetJ1_E37: J1.E37
NetJ1_E39: J1.E39
NetJ1_F4: J1.F4
NetJ1_F5: J1.F5
NetJ1_F7: J1.F7
NetJ1_F8: J1.F8
NetJ1_F10: J1.F10
NetJ1_F11: J1.F11
NetJ1_F13: J1.F13
NetJ1_F14: J1.F14
NetJ1_F15: J1.F15
NetJ1_F16: J1.F16
NetJ1_F17: J1.F17
NetJ1_F18: J1.F18
NetJ1_F19: J1.F19
NetJ1_F20: J1.F20
NetJ1_F22: J1.F22
NetJ1_F23: J1.F23
NetJ1_F25: J1.F25
NetJ1_F26: J1.F26
NetJ1_F28: J1.F28
NetJ1_F29: J1.F29
NetJ1_F31: J1.F31
NetJ1_F32: J1.F32
NetJ1_F34: J1.F34
NetJ1_F35: J1.F35
NetJ1_F37: J1.F37
NetJ1_F38: J1.F38
NetJ1_F40: J1.F40
NetJ1_G2: J1.G2
NetJ1_G3: J1.G3
NetJ1_G15: J1.G15
NetJ1_G16: J1.G16
NetJ1_G17: J1.G17
NetJ1_G18: J1.G18
NetJ1_G19: J1.G19
NetJ1_G21: J1.G21
NetJ1_G22: J1.G22
NetJ1_G24: J1.G24
NetJ1_G25: J1.G25
NetJ1_G39: J1.G39
NetJ1_H1: J1.H1
NetJ1_H4: J1.H4
NetJ1_H5: J1.H5
NetJ1_H7: J1.H7
NetJ1_H8: J1.H8
NetJ1_H10: J1.H10
NetJ1_H11: J1.H11
NetJ1_H13: J1.H13
NetJ1_H14: J1.H14
NetJ1_H15: J1.H15
NetJ1_H16: J1.H16
NetJ1_H17: J1.H17
NetJ1_H19: J1.H19
NetJ1_H20: J1.H20
NetJ1_H22: J1.H22
NetJ1_H23: J1.H23
NetJ1_H31: J1.H31 U5.2 U59.1 | length 4757.1
  Layer 7 (PWR/SIGNAL2) w4: v1(4184,788.95) 4303,788.95 v1(4315,776.95) 4441,902.95 5283.33,902.95 5764.11,422.18 6160.94,422.18 6161.9,423.14 6212.1,423.14 6213.06,422.18 6715.14,422.18 7195.92,902.95 7930,902.95 7960,872.95 8352.05,872.95 v1(8375,850)
  Bottom Copper w8: v1(4184,788.95) 4195.31,777.64 U59.1@4195.31,740.83 ; U5.2@4315,741.81 v1(4315,776.95)
NetJ1_H40: J1.H40
NetJ1_J2: J1.J2
NetJ1_J3: J1.J3
NetJ1_J5: J1.J5
NetJ1_J6: J1.J6
NetJ1_J7: J1.J7
NetJ1_J9: J1.J9
NetJ1_J10: J1.J10
NetJ1_J12: J1.J12
NetJ1_J13: J1.J13
NetJ1_J15: J1.J15
NetJ1_J16: J1.J16
NetJ1_J17: J1.J17
NetJ1_J18: J1.J18
NetJ1_J19: J1.J19
NetJ1_J21: J1.J21
NetJ1_J22: J1.J22
NetJ1_J24: J1.J24
NetJ1_J25: J1.J25
NetJ1_J27: J1.J27
NetJ1_J28: J1.J28
NetJ1_J30: J1.J30
NetJ1_J31: J1.J31
NetJ1_J33: J1.J33
NetJ1_J34: J1.J34
NetJ1_J36: J1.J36
NetJ1_J37: J1.J37
NetJ1_J39: J1.J39
NetJ1_K1: J1.K1
NetJ1_K4: J1.K4
NetJ1_K5: J1.K5
NetJ1_K7: J1.K7
NetJ1_K8: J1.K8
NetJ1_K10: J1.K10
NetJ1_K11: J1.K11
NetJ1_K12: J1.K12
NetJ1_K13: J1.K13
NetJ1_K14: J1.K14
NetJ1_K15: J1.K15
NetJ1_K16: J1.K16
NetJ1_K17: J1.K17
NetJ1_K19: J1.K19
NetJ1_K20: J1.K20
NetJ1_K22: J1.K22
NetJ1_K23: J1.K23
NetJ1_K25: J1.K25
NetJ1_K26: J1.K26
NetJ1_K28: J1.K28
NetJ1_K29: J1.K29
NetJ1_K31: J1.K31
NetJ1_K32: J1.K32
NetJ1_K34: J1.K34
NetJ1_K35: J1.K35
NetJ1_K37: J1.K37
NetJ1_K38: J1.K38
NetJ1_K40: J1.K40
NetJ1_L1: J1.L1
NetJ1_L4: J1.L4
NetJ1_L5: J1.L5
NetJ1_L8: J1.L8
NetJ1_L9: J1.L9
NetJ1_L10: J1.L10
NetJ1_L12: J1.L12
NetJ1_L13: J1.L13
NetJ1_L15: J1.L15
NetJ1_L16: J1.L16
NetJ1_L17: J1.L17
NetJ1_L19: J1.L19
NetJ1_L20: J1.L20
NetJ1_L21: J1.L21
NetJ1_L28: J1.L28
NetJ1_L29: J1.L29
NetJ1_L32: J1.L32
NetJ1_L33: J1.L33
NetJ1_L36: J1.L36
NetJ1_L37: J1.L37
NetJ1_L40: J1.L40
NetJ1_M2: J1.M2
NetJ1_M3: J1.M3
NetJ1_M6: J1.M6
NetJ1_M7: J1.M7
NetJ1_M10: J1.M10
NetJ1_M11: J1.M11
NetJ1_M14: J1.M14
NetJ1_M15: J1.M15
NetJ1_M18: J1.M18
NetJ1_M19: J1.M19
NetJ1_M22: J1.M22
NetJ1_M23: J1.M23
NetJ1_M26: J1.M26
NetJ1_M27: J1.M27
NetJ1_M30: J1.M30
NetJ1_M31: J1.M31
NetJ1_M34: J1.M34
NetJ1_M35: J1.M35
NetJ1_M38: J1.M38
NetJ1_M39: J1.M39
NetJ1_Y2: J1.Y2
NetJ1_Y3: J1.Y3
NetJ1_Y6: J1.Y6
NetJ1_Y7: J1.Y7
NetJ1_Y26: J1.Y26
NetJ1_Y27: J1.Y27
NetJ1_Y30: J1.Y30
NetJ1_Y31: J1.Y31
NetJ1_Y34: J1.Y34
NetJ1_Y35: J1.Y35
NetJ1_Y38: J1.Y38
NetJ1_Y39: J1.Y39
NetJ1_Z4: J1.Z4
NetJ1_Z5: J1.Z5
NetJ1_Z8: J1.Z8
NetJ1_Z9: J1.Z9
NetJ1_Z24: J1.Z24
NetJ1_Z25: J1.Z25
NetJ1_Z28: J1.Z28
NetJ1_Z29: J1.Z29
NetJ1_Z32: J1.Z32
NetJ1_Z33: J1.Z33
NetJ1_Z36: J1.Z36
NetJ1_Z37: J1.Z37
NetJ1_Z40: J1.Z40
NetJ3_1: J3.1 R5.1 | length 121.9
  Bottom Copper w20: R5.1@2422.02,2504 2422.02,2541.02 J3.1@2482,2601
NetJ3_2: J3.2 R198.1 R199.2 U19.5 | length 236.1
  Bottom Copper w20: U19.5@2548,2379 R198.1@2548,2454 R199.2@2548,2504 2548,2567 J3.2@2582,2601
NetJ4_1: J4.1 R6.1 | length 668.9
  Top Copper w11.5: R6.1@6227.23,2058.6 J4.1@6227.23,2727.5
NetJ12_1: J12.1 R35.2 | length 71.4
  Bottom Copper w11.5: J12.1@4425,600 4426.02,598.98 R35.2@4496.02,598.98
NetJ13_1: J13.1 R279.1 | length 1804.2
  Top Copper w11.5: J13.1@3865,600 3865,675 4100,910 4495,1305 4495,1784.95 4537,1826.95 4537,2032.95 4490.98,2078.98 v1(4483.98,2078.98)
  Bottom Copper w12: R279.1@4483.98,2058.19 v1(4483.98,2078.98)
NetJ14_3: J14.3
NetJ18_1: J18.1 R90.2 | length 70.4
  Bottom Copper w11.5: J18.1@4265,600 4266.02,598.98 R90.2@4335,598.98
NetJ19_2: J19.2 R750.2 U30.15 U32.15 U33.15 | length 8781.1
  Layer 7 (PWR/SIGNAL2) w3.3: v3@7265.01,324 7275.76,334.75 7360.75,334.75 7431,405 7555,405 7614,346 7717.02,346 7726.02,355 7738,355 v1(7740,353)
  Layer 3 (SIG1) w3.3: v1@6880,325 6895.72,340.72 6949.15,340.72 6990.65,299.22 7185.22,299.22 7210,324 v3(7264,324)
  Layer 12 (SIG4) w5: J19.2@1127,1393 1129,1391 1129,173 1220,82 3894,82 3964,152 3964,295 4084,415 4409,415 4747,77 5475,77 5830,432 5932,432 6022,522 6461,522 6591,392 6813,392 v1(6880.74,324.26)
  Bottom Copper w5: R750.2@7720.02,358 7735,358 v1(7740,353) 7745.13,347.87 U33.15@7767.76,347.87
  Bottom Copper w8: v1@6880,325 6892.87,337.87 U30.15@6957.76,337.87 ; v3(7264,324) 7272.87,332.87 U32.15@7312.76,332.87
NetJ20_4: J20.4
NetJ21_2: J21.2 U16.8 | length 361.5
  Top Copper w8: J21.2@5949,1894 6042,1987 6123,1987 6139,1971 6139,1925 6184.07,1879.93 U16.8@6200.66,1879.93
NetJ21_3: J21.3 R179.1 | length 97.2
  Bottom Copper w11.5: J21.3@5949,1994 5975.97,2020.97 R179.1@6035,2020.97
NetJ23_2: J23.2 R152.1 | length 46.4
  Bottom Copper w4: R152.1@3807,162 3852,162 J23.2@3853,161
NetJ23_4: J23.4 R158.1 | length 47
  Bottom Copper w4: R158.1@3706,161 J23.4@3753,161
NetJ23_6: J23.6 R159.1 | length 47
  Bottom Copper w4: R159.1@3606,161 J23.6@3653,161
NetJ23_8: J23.8 R161.1 | length 47
  Bottom Copper w4: R161.1@3506,161 J23.8@3553,161
NetJ26_1: J26.1 R196.1 | length 268.1
  Top Copper w11.5: R196.1@6449.48,1844.93 6633.93,1844.93 6657,1868 J26.1@6708,1868
NetJ26_3: J26.3 R194.1 | length 330.2
  Top Copper w11.5: R194.1@6449.48,1894.93 6534.93,1894.93 J26.3@6708,2068
NetL8_2: L8.2 U6.39 | length 59.6
  Bottom Copper w11.5: 6959.6,2380.09 ccw(c6987.09,2407.57) U6.39@6987.09,2368.7
  Bottom Copper w15.5: L8.2@6949.69,2405 6949.69,2390 6959.6,2380.09
NetL9_2: L9.2 U6.42 | length 42.5
  Bottom Copper w11.5: 6965.43,2427.76 U6.42@6987.09,2427.76
  Bottom Copper w15.5: L9.2@6949.69,2440 6953.19,2440 6965.43,2427.76
NetL10_2: L10.2 U6.45 U6.47 | length 109.9
  Bottom Copper w10: L10.2@6955.5,2487.41 U6.45@6987.09,2487.41
  Bottom Copper w11.5: L10.2@6954.06,2486.81 ccw(c6954.06,2480.63) L10.2@6949.68,2485 6949.68,2514.68 6961.18,2526.18 U6.47@6987.09,2526.18
  Bottom Copper w15.5: L10.2@6954.06,2486.81 cw(c6955.5,2485.37) L10.2@6955.5,2487.41
NetR11_1: R11.1 R13.1 R22.2 | length 34
  Top Copper w9: R22.2@6221,1098.99 R11.1@6221,1133.01
NetR12_2: R12.2 R15.1 R23.2 | length 34
  Top Copper w9: R23.2@6253,1098.99 R15.1@6253,1133.01
NetR24_1: R24.1 TP2.1 U4.14 | length 234.2
  Bottom Copper w9: TP2.1@5059.25,160.47 5059.25,284.25 5085,310 5107.99,310 R24.1@5110,307.99 5128.2,326.19 U4.14@5128.2,348.67
NetR25_1: R25.1 TP3.1 U4.11 | length 225.6
  Bottom Copper w9: TP3.1@5174.25,165.47 5220,211.22 5220,282.83 5209.84,292.99 R25.1@5197.96,292.99 ; U4.11@5187.25,348.67 5187.25,303.7 R25.1@5197.96,292.99 ; R25.1@5195,292.99 R25.1@5197.96,292.99
NetR31_1: R31.1 U6.6 | length 67.8
  Top Copper w11.5: R31.1@7331.02,2435 7351.36,2435 ccw(c7351.36,2443.64) v1@7357.46,2437.52 ; v1@7357.47,2437.53 7358.09,2438.15 v1(7364.24,2438.15)
  Bottom Copper w11.5: U6.6@7333.54,2447.44 cw(c7333.54,2413.6) 7357.47,2437.53 7358.09,2438.15 v1(7364.24,2438.15)
NetR34_1: R34.1 U6.59 | length 42
  Bottom Copper w10: U6.59@7209.53,2571.46 R34.1@7209.53,2613.5
NetR37_1: R37.1 R45.2 U6.1 | length 131.1
  Bottom Copper w7: U6.1@7333.54,2546.46 7346.61,2546.46 ccw(c7353.47,2553.33) 7353.47,2543.62 7424.62,2543.62 ccw(c7424.62,2559.31) R45.2@7435.71,2548.21 ; R45.2@7438.19,2550.1 7438.19,2550 R37.1@7465,2550
NetR38_1: R38.1 R47.2 U6.24 | length 145.8
  Bottom Copper w7: U6.24@7170.16,2225.6 7170.16,2214.31 ccw(c7177.02,2207.44) 7167.32,2207.44 7167.31,2201 ccw(c7206.7,2201) 7178.84,2173.16 7180,2172 cw(c7146.2,2138.2) 7194,2138.2 7194,2128 ccw(c7212.55,2128) 7199.43,2114.88 R47.2@7200.38,2113.93 ccw(c7202.28,2112.03) 7199.59,2112.03 R38.1@7199.59,2089.96
NetR39_1: R39.1 R57.2 U6.29 | length 174.8
  Bottom Copper w7: R39.1@6968.86,2113.09 6992.48,2113.09 cw(c6992.48,2109.53) R57.2@6995,2112.05 6999.84,2116.89 cw(c7005,2111.72) 7005,2119.02 ccw(c7005,2145.15) 7023.48,2126.68 7036.36,2139.57 ccw(c7017.93,2158) 7044,2158 cw(c7063.31,2158) 7049.66,2171.66 7060.33,2182.33 ccw(c7039.65,2203) 7068.89,2203 7068.89,2207.44 cw(c7078.59,2207.44) 7071.73,2214.31 U6.29@7071.73,2225.6
NetR40_1: R40.1 R46.2 U6.2 | length 135.4
  Bottom Copper w7: U6.2@7333.54,2526.78 7346.75,2526.78 cw(c7353.61,2519.92) 7353.61,2529.62 7424.12,2529.62 cw(c7424.12,2513.7) 7435.38,2524.96 R46.2@7438.19,2522.15 7458.11,2522.15 ccw(c7458.11,2531.89) R40.1@7465,2525
NetR41_1: R41.1 R48.2 U6.25 | length 146.7
  Bottom Copper w7: U6.25@7150.47,2225.6 7150.47,2214.31 cw(c7143.61,2207.44) 7153.32,2207.44 7153.31,2201 ccw(c7206.7,2201) 7168.95,2163.25 7170.1,2162.1 cw(c7146.2,2138.2) 7180,2138.2 7180,2128 cw(c7164.32,2128) 7175.41,2116.91 R48.2@7172.43,2113.93 cw(c7167.2,2108.71) 7174.59,2108.71 R41.1@7174.59,2089.96
NetR42_1: R42.1 R50.2 U6.15 | length 89.7
  Bottom Copper w7: U6.15@7333.54,2270.87 7346.07,2270.87 cw(c7346.07,2268.17) 7347.98,2270.08 ccw(c7352.93,2275.03) 7350.56,2268.44 ccw(c7352.93,2275.03) 7352.93,2268.03 7378.17,2268.03 ccw(c7378.17,2291.83) R50.2@7395,2275 7415,2275 R42.1@7418.98,2271.02
NetR43_1: R43.1 U6.5 | length 56
  Top Copper w11.5: R43.1@7331.02,2465 v1(7360,2465)
  Bottom Copper w11.5: U6.5@7333.54,2467.13 7354.87,2467.13 cw(c7354.87,2459.87) v1(7360,2465)
NetR44_1: R44.1 R52.2 U6.16 | length 88.5
  Bottom Copper w7: U6.16@7333.54,2251.19 7346.76,2251.19 ccw(c7346.76,2253.52) 7348.41,2251.87 cw(c7353.62,2246.66) 7351.3,2253.65 cw(c7353.62,2246.66) 7353.62,2254.03 7378.14,2254.03 cw(c7378.14,2230.19) R52.2@7395,2247.05 7417.95,2247.05 R44.1@7418.98,2246.02
NetR49_1: R49.1 R58.2 U6.30 | length 153.1
  Bottom Copper w7: R49.1@6968.86,2138.09 6990.39,2138.09 ccw(c6990.39,2144.61) R58.2@6995,2140 6999.84,2135.16 ccw(c7005,2140.32) 7005,2133.02 ccw(c7005,2145.15) 7013.57,2136.57 ; 7013.58,2136.58 7026.46,2149.46 ccw(c7017.93,2158) 7030,2158 cw(c7063.31,2158) 7039.76,2181.56 7050.43,2192.23 ccw(c7039.65,2203) 7054.89,2203 7054.89,2207.44 ccw(c7045.18,2207.44) 7052.05,2214.31 U6.30@7052.05,2225.6
NetR51_1: R51.1 R55.2 U6.3 | length 164
  Bottom Copper w7: U6.3@7333.54,2507.09 7344.83,2507.09 ccw(c7351.7,2513.96) 7351.7,2504.25 7372.08,2504.25 cw(c7372.08,2462.08) 7401.9,2491.9 7404.17,2489.63 ccw(c7425,2510.46) 7425,2481 7426.93,2481 cw(c7426.93,2449.93) 7448.9,2471.9 ccw(c7454.06,2477.06) 7454.06,2469.76 R55.2@7463.06,2469.76 ccw(c7465.45,2469.76) 7463.76,2468.07 R51.1@7479.52,2452.31
NetR53_1: R53.1 R56.2 U6.4 | length 153.4
  Bottom Copper w7: U6.4@7333.54,2487.41 7345.36,2487.41 ccw(c7345.36,2495.78) 7351.28,2489.86 cw(c7353.63,2483.03) 7353.63,2490.25 7372.08,2490.25 cw(c7372.08,2462.08) 7392,2482 7394.27,2479.73 ccw(c7425,2510.46) 7425,2467 7426.93,2467 cw(c7426.93,2449.93) 7439,2462 cw(c7432.18,2455.18) 7441.83,2455.18 R56.2@7441.83,2448.53 7451.4,2438.96 ccw(c7461.84,2449.39) R53.1@7461.84,2434.63
NetR61_1: R61.1 U6.57 U49.1 | length 860.5
  Top Copper w10.5: v1(7676,2645) 7676.5,2644.5 7707.19,2644.5 cw(c7707.19,2629.22) R61.1@7718,2640.02 7726.99,2640.02 ccw(c7726.99,2657.01) 7739,2645 cw(c7763.14,2620.86) 7763.14,2655 U49.1@7777.72,2655
  Layer 3 (SIG1) w3.25: v1(7104,2675.57) ccw(c7126.63,2698.2) 7126.63,2666.19 7141.49,2666.19 ccw(c7141.49,2706.51) 7170,2678 cw(c7214.06,2633.94) 7214.06,2696.25 7482.58,2696.25 cw(c7482.58,2585) 7561.24,2663.67 7562.95,2661.95 ccw(c7628.03,2727.03) 7628.03,2635 7662,2635 ccw(c7662,2644.66) 7668.83,2637.83 v1(7676,2645)
  Bottom Copper w7: v1(7104,2675.57) 7108.45,2671.12 ccw(c7116.7,2679.37) 7116.7,2667.7 7140.29,2667.7 cw(c7140.29,2642.09) 7158.4,2660.2 cw(c7136.88,2638.68) 7167.31,2638.68 7167.31,2590.21 ccw(c7177.02,2590.21) 7170.16,2583.34 U6.57@7170.16,2572.05
NetR61_2: R61.2 U6.56 U49.2 | length 837.8
  Top Copper w10.5: v1(7676,2615) 7677.5,2613.5 7707.19,2613.5 ccw(c7707.19,2628.78) R61.2@7718,2617.98 7721.74,2617.98 cw(c7721.74,2590.74) 7741,2610 ccw(c7753.07,2622.07) 7753.07,2605 U49.2@7777.72,2605
  Layer 3 (SIG1) w3.25: v1(7104,2645.57) cw(c7126.63,2622.93) 7126.63,2654.94 7141.49,2654.94 ccw(c7141.49,2706.51) 7177.96,2670.04 cw(c7214.06,2633.94) 7214.06,2685 7482.58,2685 cw(c7482.58,2585) 7553.29,2655.71 7555,2654 ccw(c7628.03,2727.03) 7628.03,2623.75 7662,2623.75 cw(c7662,2611.08) 7670.96,2620.04 v1(7676,2615)
  Bottom Copper w7: v1(7104,2645.57) 7108.89,2650.46 cw(c7116.71,2642.64) 7116.71,2653.7 7140.29,2653.7 cw(c7140.29,2642.09) 7148.5,2650.3 cw(c7136.88,2638.68) 7153.31,2638.68 7153.31,2592.13 cw(c7145.91,2592.13) 7152.94,2589.81 cw(c7145.91,2592.13) 7151.15,2586.9 ccw(c7160.18,2583.34) 7150.47,2583.34 U6.56@7150.47,2572.05
NetR62_1: R62.1 R64.2 U6.27 | length 109.6
  Bottom Copper w7: U6.27@7111.1,2225.6 7111.1,2214.31 ccw(c7117.96,2207.44) 7108.26,2207.44 7108.26,2158.54 ccw(c7121.11,2158.54) 7112.02,2149.45 R64.2@7116.48,2145 7116.48,2123.56 cw(c7111.44,2123.56) R62.1@7115,2120
NetR63_1: R63.1 R65.2 U6.28 | length 108.3
  Bottom Copper w7: R63.1@7090,2120 cw(c7093.56,2123.56) 7088.52,2123.56 R65.2@7088.52,2145 7088.74,2145.22 ccw(c7075.42,2158.54) 7094.26,2158.54 7094.26,2207.44 ccw(c7084.55,2207.44) 7091.42,2214.31 U6.28@7091.42,2225.6
NetR66_1: R66.1 U6.61 U49.4 | length 679.8
  Top Copper w10.5: v1(7254.12,2645.83) cw(c7276.55,2645.83) 7254.62,2650.54 cw(c7276.55,2645.83) 7260.68,2661.68 7266,2667 cw(c7292.56,2640.44) 7292.56,2678 7332.51,2678 cw(c7332.51,2657.51) 7347,2672 ccw(c7407.36,2732.36) 7407.36,2647 7472.65,2647 cw(c7472.65,2547) 7543.36,2617.71 7623.66,2537.42 ccw(c7681.63,2601.29) 7679.16,2515.07 ; 7681.63,2515.03 cw(c7681.63,2601.29) 7679.16,2515.07 ; U49.4@7777.72,2505 7748.74,2505 cw(c7748.74,2526.1) 7733.82,2511.18 ccw(c7715,2492.36) R66.1@7715,2518.98 cw(c7702.99,2530.99) 7702.99,2514 7695,2514 cw(c7695,2632.3) 7679.16,2515.07
  Bottom Copper w7: U6.61@7248.9,2572.05 7248.9,2583.34 cw(c7255.76,2590.21) 7246.06,2590.21 7246.06,2633.8 cw(c7255.62,2633.8) 7248.85,2640.56 v1(7254.12,2645.83)
NetR66_2: R66.2 U6.60 U49.3 | length 726.4
  Top Copper w10.5: v1@7223.12,2645.83 cw(c7276.55,2645.83) 7223.62,2653.12 cw(c7276.55,2645.83) 7238.77,2683.61 7244.08,2688.92 cw(c7292.56,2640.44) 7292.56,2709 7332.51,2709 cw(c7332.51,2657.51) 7368.92,2693.92 ccw(c7407.36,2732.36) 7407.36,2678 7472.65,2678 cw(c7472.65,2547) 7565.28,2639.63 7644.99,2559.93 ; 7645.58,2559.34 7644.99,2559.93 ; U49.3@7777.72,2555 7759.14,2555 ccw(c7759.14,2520.86) 7735,2545 cw(c7725.4,2554.6) 7725.4,2541.02 R66.2@7715,2541.02 ccw(c7705.4,2531.42) 7705.4,2545 7695,2545 cw(c7695,2632.3) 7681.63,2546.03 cw(c7681.63,2601.29) 7644.99,2559.93
  Bottom Copper w7: v1(7224.12,2645.83) 7229.16,2640.79 cw(c7222.17,2633.8) 7232.06,2633.8 7232.06,2592.13 cw(c7224.65,2592.13) 7231.68,2589.81 cw(c7224.65,2592.13) 7229.89,2586.9 ccw(c7238.92,2583.34) 7229.21,2583.34 U6.60@7229.21,2572.05
NetR67_1: R67.1 U36.1 | length 95.6
  Top Copper w11.5: R67.1@4682,477.99 4682,493.79 4700.22,512.01 v1(4717.99,512.01)
  Bottom Copper w11.5: v1@4717.2,512.8 v1(4717.99,512.01) U36.1@4717.99,476.85
NetR68_1: R68.1 U36.7 | length 87.3
  Top Copper w11.5: R68.1@4742.99,261.57 4742.99,249.01 v1(4767.99,224.01)
  Bottom Copper w11.5: v1@4767.2,224.8 v1(4767.99,224.01) U36.7@4767.99,262.28
NetR70_2: R70.2 U52.20 | length 47.7
  Top Copper w5: U52.20@5711.61,1319.2 5711.61,1304.39 5717.21,1298.79 R70.2@5742.21,1298.79
NetR86_1: R86.1 U32.1 | length 36.5
  Bottom Copper w8: R86.1@7333.98,390 7336.38,387.6 U32.1@7336.38,354.53
NetR86_2: R86.2 R305.2 U13.12 | length 258.4
  Top Copper w11.5: v1(7168.62,325) 7194,325 7236,367 7285.98,367 v3(7335,416.02)
  Bottom Copper w8: R305.2@7156.02,325 v1(7168.62,325) ; R305.2@7157.13,325.12 U13.12@7157.13,366.85
NetR94_2: R94.2 U7.19 U8.14 | length 1908.9
  Top Copper w9: R94.2@3140,1787.99 v1(3140.32,1788.31) U8.14@3182.04,1788.31
  Top Copper w9.8: v1(1790,1710) 1800.32,1699.69 U7.19@1833.46,1699.68
  Bottom Copper w11.5: v1(1790,1710) 1790,1952 1841.5,2003.5 2098.5,2003.5 2173,1929 2617,1929 2682,1994 3041,1994 3140.32,1894.68 v1(3140.32,1788.31)
NetR95_1: R95.1 R950.1 U7.18 | length 111.7
  Top Copper w9.8: R950.1@1758.17,1703.43 1769.25,1714.51 1769.25,1736.26 R95.1@1772.99,1740 1795,1740 1815.63,1719.37 U7.18@1833.46,1719.37
NetR98_1: R98.1 U8.2 | length 61.1
  Top Copper w9: U8.2@3311.96,1788.31 3369.57,1788.31 R98.1@3372.01,1790.75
